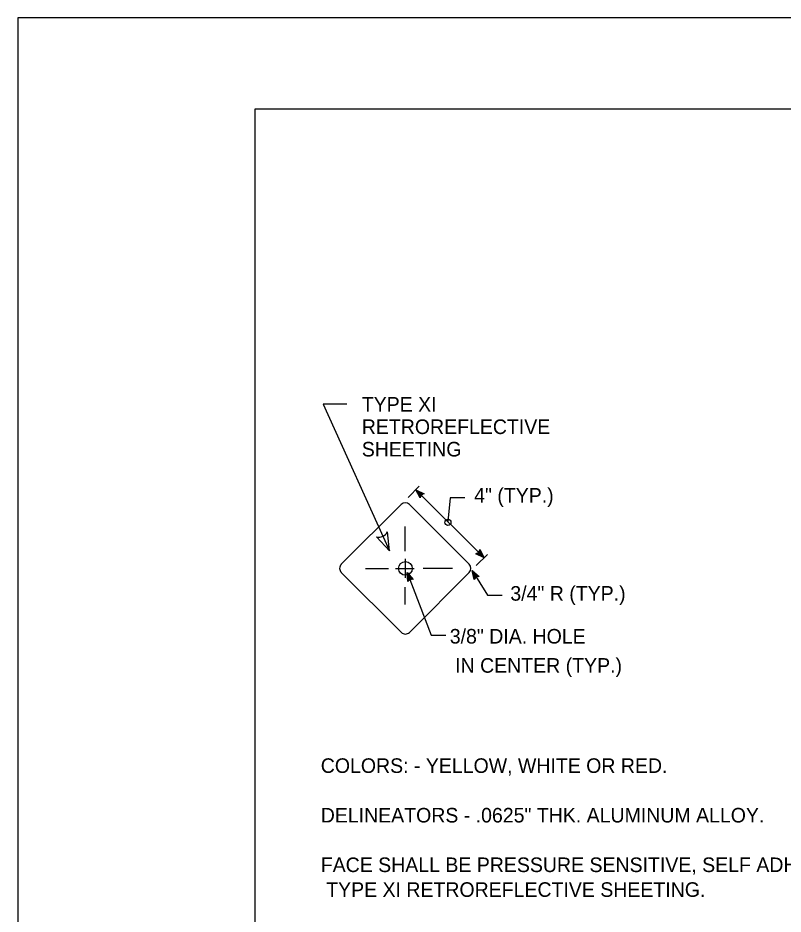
# Model space of a CAD drawing. Extents: x -0.14 to 2.7, y -0.05 to 1.78.
# Drawn here: x -0.135 to 0.302, y 1.269 to 1.781 of the extents above; entities that cross this region are included whole.
import ezdxf

# ---------------------------------------------------------------- set-up
doc = ezdxf.new("R2010")
doc.units = 0
for name, color, linetype in [('BDR_Outer_Perimeter', 7, 'Continuous'), ('BDR_Perimeter', 7, 'Continuous'), ('CT_CSHT_GeneralLabel', 7, 'Continuous')]:
    doc.layers.add(name, color=color, linetype=linetype)

msp = doc.modelspace()

# ---------------------------------------------------------------- linework, layer by layer
at = {"layer": 'BDR_Outer_Perimeter'}
msp.add_lwpolyline([(-0.13539433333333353, -0.052081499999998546), (2.697933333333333, -0.052081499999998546), (2.697933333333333, 1.7812481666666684), (-0.13539433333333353, 1.7812481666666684)], close=True, dxfattribs=at)
at = {"layer": 'BDR_Perimeter'}
for p, q in [((0, 1.7291666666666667), (-6.111028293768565e-16, 1.6805327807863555e-15)), ((2.64583333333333, 1.7291666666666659), (0, 1.7291666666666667))]:
    msp.add_line(p, q, dxfattribs=at)
at = {"layer": 'CT_CSHT_GeneralLabel'}
for p, q in [((0.08757226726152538, 1.5071496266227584), (0.09400351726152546, 1.5135808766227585)), ((0.09204657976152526, 1.5116221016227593), (0.13099974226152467, 1.4726671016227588)), ((0.09440409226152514, 1.5068960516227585), (0.09204657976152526, 1.5116221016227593)), ((0.09204657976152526, 1.5116221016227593), (0.09677262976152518, 1.5092554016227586)), ((0.09204657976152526, 1.5116221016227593), (0.0951740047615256, 1.5084542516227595)), ((0.09204657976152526, 1.5116221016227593), (0.09473484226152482, 1.5079085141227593)), ((0.09204657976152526, 1.5116221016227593), (0.09589246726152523, 1.5089705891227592)), ((0.09204657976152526, 1.5116221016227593), (0.09455844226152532, 1.5075263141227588)), ((0.09204657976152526, 1.5116221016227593), (0.09495901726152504, 1.5082208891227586)), ((0.09204657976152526, 1.5116221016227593), (0.0954790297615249, 1.5087390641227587)), ((0.09204657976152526, 1.5116221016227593), (0.09626364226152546, 1.5091433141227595)), ((0.08362531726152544, 1.503200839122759), (0.04944230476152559, 1.4690196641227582)), ((0.1225307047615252, 1.4690196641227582), (0.0883513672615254, 1.503200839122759)), ((0.08599017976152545, 1.4765019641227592), (0.08599017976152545, 1.4906488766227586)), ((0.07688174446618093, 1.4767223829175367), (0.07577857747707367, 1.4874731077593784)), ((0.06954877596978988, 1.4846610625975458), (0.07688174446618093, 1.4767223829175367)), ((0.06954877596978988, 1.4846610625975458), (0.06954877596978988, 1.4846610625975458)), ((0.13099974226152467, 1.4726671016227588), (0.12627369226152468, 1.4750301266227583)), ((0.13099974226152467, 1.4726671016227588), (0.1267826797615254, 1.4751458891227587)), ((0.13099974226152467, 1.4726671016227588), (0.1271483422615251, 1.4753167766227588)), ((0.13099974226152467, 1.4726671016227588), (0.127563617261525, 1.4755501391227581)), ((0.13099974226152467, 1.4726671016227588), (0.12786680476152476, 1.4758312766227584)), ((0.13099974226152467, 1.4726671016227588), (0.12808179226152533, 1.476064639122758)), ((0.13099974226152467, 1.4726671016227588), (0.1283059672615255, 1.4763806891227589)), ((0.13099974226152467, 1.4726671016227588), (0.12848604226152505, 1.4767610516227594)), ((0.1286367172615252, 1.4773913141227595), (0.13099974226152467, 1.4726671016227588)), ((0.08599017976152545, 1.472190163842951), (0.08599017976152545, 1.461291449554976)), ((0.1264776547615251, 1.4682387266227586), (0.13291074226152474, 1.4746754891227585)), ((0.06327132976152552, 1.466614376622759), (0.07644423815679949, 1.466614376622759)), ((0.08039617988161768, 1.466614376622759), (0.0910478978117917, 1.466614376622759)), ((0.08599017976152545, 1.466614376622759), (0.08599017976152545, 1.466614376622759)), ((0.11292976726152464, 1.466614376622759), (0.09620300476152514, 1.466614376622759)), ((0.12543762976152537, 1.4602750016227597), (0.12416056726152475, 1.4654053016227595)), ((0.12416056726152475, 1.4654053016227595), (0.12825819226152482, 1.4620684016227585)), ((0.12416056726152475, 1.4654053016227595), (0.12652726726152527, 1.4616365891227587)), ((0.12416056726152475, 1.4654053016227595), (0.12597969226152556, 1.4611937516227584)), ((0.12416056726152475, 1.4654053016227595), (0.1273394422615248, 1.4619820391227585)), ((0.12416056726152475, 1.4654053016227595), (0.1257224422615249, 1.460859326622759)), ((0.12416056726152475, 1.4654053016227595), (0.12626817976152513, 1.4614473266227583)), ((0.12416056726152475, 1.4654053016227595), (0.12688190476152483, 1.4618423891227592)), ((0.12416056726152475, 1.4654053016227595), (0.1277381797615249, 1.4620628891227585)), ((0.04944230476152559, 1.4642954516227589), (0.08362531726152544, 1.4301179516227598)), ((0.08739402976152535, 1.459102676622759), (0.08716250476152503, 1.464379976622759)), ((0.08716250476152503, 1.464379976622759), (0.09051594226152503, 1.4602897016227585)), ((0.08716250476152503, 1.464379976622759), (0.08873172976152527, 1.4602125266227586)), ((0.08716250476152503, 1.464379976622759), (0.08810881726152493, 1.4598891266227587)), ((0.08716250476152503, 1.464379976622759), (0.08959719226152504, 1.4603926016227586)), ((0.08716250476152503, 1.464379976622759), (0.08778725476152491, 1.4596153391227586)), ((0.08716250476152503, 1.464379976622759), (0.08844140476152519, 1.4600839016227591)), ((0.08716250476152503, 1.464379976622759), (0.08912127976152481, 1.4603448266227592)), ((0.08716250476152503, 1.464379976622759), (0.0900032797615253, 1.4603926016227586)), ((0.0883513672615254, 1.4301142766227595), (0.1225307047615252, 1.4642954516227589)), ((0.08599017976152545, 1.4460748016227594), (0.08599017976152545, 1.4559513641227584))]:
    msp.add_line(p, q, dxfattribs=at)
for points in [[(0.05257079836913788, 1.5604468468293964), (0.03908969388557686, 1.5604468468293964), (0.07688174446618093, 1.4767223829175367)], [(0.12002067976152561, 1.506995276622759), (0.11166556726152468, 1.506995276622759), (0.11031684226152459, 1.49346208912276)], [(0.12416056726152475, 1.4654053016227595), (0.13307060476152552, 1.4513741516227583), (0.1414257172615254, 1.4513741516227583)], [(0.08716250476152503, 1.464379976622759), (0.10085004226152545, 1.4285909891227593), (0.10920331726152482, 1.4285909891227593)]]:
    msp.add_lwpolyline(points, dxfattribs=at)
for centre, radius in [((0.11034779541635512, 1.4929819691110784), 0.0017651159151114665), ((0.08604346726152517, 1.4666143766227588), 0.003915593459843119)]:
    msp.add_circle(centre, radius, dxfattribs=at)
for centre, radius, start, end in [((0.09712144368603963, 1.5065425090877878), 0.002738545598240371, 97.39918333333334, 172.60081388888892), ((0.08598744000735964, 1.500839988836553), 0.003341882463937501, 45.00719722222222, 135), ((0.07083734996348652, 1.490111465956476), 0.005601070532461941, 256.6929332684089, 331.8945638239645), ((0.12591847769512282, 1.4777454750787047), 0.0027385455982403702, 277.3991833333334, 352.6008138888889), ((0.051807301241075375, 1.466659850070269), 0.0033418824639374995, 134.99999722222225, 225.00528611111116), ((0.12016775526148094, 1.466660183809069), 0.0033418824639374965, 315, 44.98661388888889), ((0.08972754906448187, 1.45767017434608), 0.0027385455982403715, 73.32869444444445, 148.530325), ((0.12800896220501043, 1.4593401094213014), 0.0027385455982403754, 84.82044444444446, 160.02207500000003), ((0.08598784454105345, 1.4324797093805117), 0.0033418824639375, 224.98983055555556, 314.9931666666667)]:
    msp.add_arc(centre, radius, start, end, dxfattribs=at)

# ---------------------------------------------------------------- texts
for s, p in [('TYPE XI', (0.06113451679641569, 1.5562819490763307)), ('RETROREFLECTIVE', (0.06113451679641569, 1.5434486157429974)), ('SHEETING', (0.06113451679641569, 1.530615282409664)), ('4" (TYP.)', (0.12536193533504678, 1.5042286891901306)), ('3/4" R (TYP.)', (0.14602626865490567, 1.4482088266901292)), ('3/8" DIA. HOLE', (0.11142650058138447, 1.4237031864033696)), (' IN CENTER (TYP.)', (0.11142650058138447, 1.4070365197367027)), ('COLORS: - YELLOW, WHITE OR RED.', (0.037689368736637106, 1.3497727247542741)), ('DELINEATORS - .0625" THK. ALUMINUM ALLOY.', (0.037689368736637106, 1.321439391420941)), ('FACE SHALL BE PRESSURE SENSITIVE, SELF ADHERING, ', (0.037689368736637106, 1.2931060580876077)), (' TYPE XI RETROREFLECTIVE SHEETING.', (0.037689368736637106, 1.278939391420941))]:
    msp.add_text(s, height=0.008333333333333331, dxfattribs=at).set_placement(p)

doc.saveas('drawing.dxf')
